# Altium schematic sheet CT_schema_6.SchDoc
size 146 x 119 mm
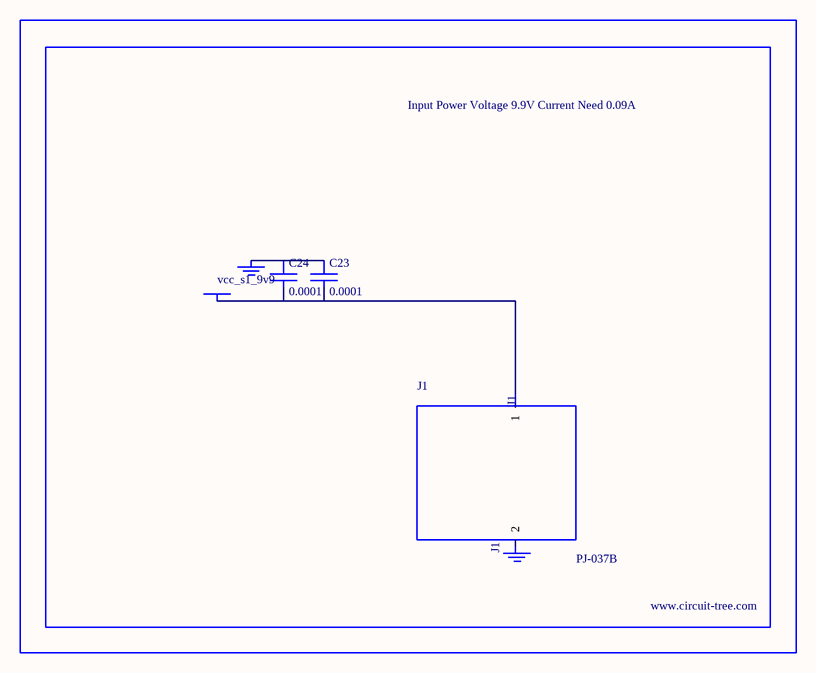
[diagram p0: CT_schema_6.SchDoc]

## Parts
BORDER5  (no value)
C23  0.0001  [EXV-9H]
C24  0.0001  [EXV-9H]
GND_INSTANCE_5_0  (no value)
GND_INSTANCE_5_1  (no value)
J1  PJ-037B  [PJ-037B_PACKAGE]
POWER_INSTANCE_5_0  vcc_s1_9v9

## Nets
NetC23_1: C23.1 C24.1 GND_INSTANCE_5_0.0(GND)
NetC23_2: C23.2 C24.2 J1.1 POWER_INSTANCE_5_0.0(PWR)

Not connected (* = marked no-connect by the designer): GND_INSTANCE_5_1 0(GND); J1 2

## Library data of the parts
BORDER5 = BORDER_PAGE5
C23 C24 = EDK107M035A9HAA
GND_INSTANCE_5_0 GND_INSTANCE_5_1 = GND
POWER_INSTANCE_5_0 = PWR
